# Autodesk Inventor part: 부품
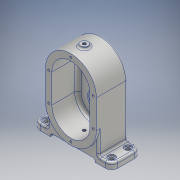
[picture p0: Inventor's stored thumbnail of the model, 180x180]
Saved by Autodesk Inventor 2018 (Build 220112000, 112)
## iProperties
Created: 2021-05
Part Number: 부품
Material: 알루미늄 6061
Document SubType Name: Modeling
Designer: admin
Density: 2.7 g/cm^3
Appearance: 알루미늄 - 평지
Mass: 756.755 g
Surface Area: 581.829 cm^2
Volume: 280.28 cm^3
Author: admin
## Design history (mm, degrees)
sketch "스케치1"
  geometry: L1 (85.4, 0)-(-85.4, 0) reference; L2 (0, -74.9)-(0, 109.9) reference; L3 (40, 43.5)-(40, -38.5); L4 (40, -38.5)-(61, -38.5); L5 (61, -38.5)-(61, -48.5); L6 (61, -48.5)-(35, -48.5); L7 (35, -48.5)-(35, -43.5); L8 (35, -43.5)-(0, -43.5); L9 (-40, 43.5)-(-40, -38.5); L10 (-40, -38.5)-(-61, -38.5); L11 (-61, -38.5)-(-61, -48.5); L12 (-61, -48.5)-(-35, -48.5); L13 (-35, -48.5)-(-35, -43.5); L14 (-35, -43.5)-(0, -43.5); L15 (40, 43.5)-(-40, 43.5); A1 r 40 centre (0, 43.5) between (40, 43.5) and (-40, 43.5); 1 further point
  constraints: 26 end point, 6 symmetric about line, 5 perpendicular, 2 point on circle, 1 centre point, 1 horizontal, 1 midpoint, 1 point on line, 1 vertical, 1 other
  dimensions: "d0" = 70 distance between parallel lines of L13 L7; "d1" = 10 distance between parallel lines of L6 L4; "d2" = 122 distance between parallel lines of L11 L5; "d4" = 5 distance of L12.end L13.end; "d5" = 80 distance of L3.start L9.start; "d6" = 92 distance between parallel lines of L12 L15
extrude "돌출1" new body sketch "스케치1" stored distance "d7" = 46; taper "d8" = 0 deg
sketch "스케치2"
  geometry: L1 (40, -43.5)-(40, 38.5) reference; L2 (40, 38.5)-(61, 38.5) reference; L3 (61, 38.5)-(61, 48.5) reference; L4 (61, 48.5)-(35, 48.5) reference; L5 (35, 48.5)-(35, 43.5) reference; L6 (35, 43.5)-(-35, 43.5) reference; L7 (-35, 43.5)-(-35, 48.5) reference; L8 (-35, 48.5)-(-61, 48.5) reference; L9 (-61, 48.5)-(-61, 38.5) reference; L10 (-61, 38.5)-(-40, 38.5) reference; L11 (-40, 38.5)-(-40, -43.5) reference; L12 (-85.4, 0)-(85.4, 0) reference; L13 (0, 74.9)-(0, -109.9) reference; L14 (0, 1.5)-(0, -43.5); L15 (26, 1.5)-(26, -43.5); L16 (-26, -43.5)-(-26, 1.5); A1 r 40 centre (0, -43.5) between (-40, -43.5) and (40, -43.5) reference; A2 r 26 centre (0, 1.5) between (26, 1.5) and (-26, 1.5); A3 r 26 centre (0, -43.5) between (-26, -43.5) and (26, -43.5); 2 further points
  constraints: 8 end point, 4 point on circle, 4 tangent, 2 centre point, 2 point on line, 1 coincident, 1 midpoint, 1 parallel
  dimensions: "d9" = 26 radius of A3; "d11" = 45 distance of L14.start A1.centre
extrude "돌출2" join sketch "스케치2" distance "d12" = 8; taper "d13" = 0 deg
sketch "스케치3"
  geometry: L1 (26, -43.5)-(26, 1.5) reference; L2 (-26, 1.5)-(-26, -43.5) reference; L3 (-85.4, 0)-(85.4, 0) reference; L4 (0, 74.9)-(0, -109.9) reference; L5 (26, -43.5)-(26, 1.5) reference; L6 (26, -13.5)-(-26, -13.5); L7 (-26, -13.5)-(-26, 1.5); L8 (-26, 1.5)-(26, 1.5); L9 (26, 1.5)-(26, -13.5); A1 r 26 centre (0, 1.5) between (26, 1.5) and (-26, 1.5) reference; A2 r 26 centre (0, -43.5) between (-26, -43.5) and (26, -43.5) reference; A3 r 26 centre (0, 1.5) between (26, 1.5) and (-26, 1.5); 1 further point
  constraints: 8 end point, 2 parallel, 2 point on circle, 1 centre point, 1 coincident, 1 horizontal, 1 perpendicular, 1 point on line
  dimensions: "d14" = 30 distance from line of L6 A2.centre
extrude "돌출3" join sketch "스케치3" distance "d15" = 3; taper "d16" = 0 deg
sketch "스케치4"
  geometry: L1 (-40, 43.5)-(-40, -38.5) reference; L2 (-40, -38.5)-(-61, -38.5) reference; L3 (-61, -38.5)-(-61, -48.5) reference; L4 (-61, -48.5)-(-35, -48.5) reference; L5 (-35, -48.5)-(-35, -43.5) reference; L6 (-35, -43.5)-(35, -43.5) reference; L7 (35, -43.5)-(35, -48.5) reference; L8 (35, -48.5)-(61, -48.5) reference; L9 (61, -48.5)-(61, -38.5) reference; L10 (61, -38.5)-(40, -38.5) reference; L11 (40, -38.5)-(40, 43.5) reference; L12 (-85.4, 0)-(85.4, 0) reference; L13 (0, -74.9)-(0, 109.9) reference; L14 (0, 43.5)-(0, -1.5); L15 (-40, 43.5)-(-40, -1.5); L16 (40, -1.5)-(40, 43.5); A1 r 40 centre (0, 43.5) between (40, 43.5) and (-40, 43.5) reference; A2 r 40 centre (0, 43.5) between (40, 43.5) and (-40, 43.5); A3 r 40 centre (0, -1.5) between (-40, -1.5) and (40, -1.5); 2 further points
  constraints: 8 end point, 4 point on circle, 4 tangent, 2 centre point, 1 concentric, 1 midpoint, 1 parallel, 1 point on line
  dimensions: "d17" = 45 distance of L14.end L14.start
extrude "돌출4" join sketch "스케치4" distance "d18" = 3; taper "d19" = 0 deg
sketch "스케치5"
  geometry: L1 (-40, 43.5)-(-40, -1.5) reference; L2 (40, -1.5)-(40, 43.5) reference; L3 (0, -74.9)-(0, 109.9) reference; L4 (-85.4, 0)-(85.4, 0) reference; L5 (0, -1.5)-(0, 43.5); L6 (30, -1.5)-(30, 43.5); L7 (-30, 43.5)-(-30, -1.5); A1 r 40 centre (0, -1.5) between (-40, -1.5) and (40, -1.5) reference; A2 r 40 centre (0, 43.5) between (40, 43.5) and (-40, 43.5) reference; A3 r 30 centre (0, -1.5) between (-30, -1.5) and (30, -1.5); A4 r 30 centre (0, 43.5) between (30, 43.5) and (-30, 43.5); 2 further points
  constraints: 8 end point, 4 point on circle, 4 tangent, 2 centre point, 1 midpoint, 1 parallel, 1 perpendicular
  dimensions: "d20" = 30 radius of A4
extrude "돌출5" cut sketch "스케치5" distance "d21" = 41; taper "d22" = 0 deg
sketch "스케치6"
  geometry: L1 (30, 43.5)-(30, -1.5) reference; L2 (-30, -1.5)-(-30, 43.5) reference; L3 (-85.4, 0)-(85.4, 0) reference; L4 (0, -74.9)-(0, 109.9) reference; C1 r 14 at (0, 43.5); C2 r 14 at (0, -1.5); A1 r 30 centre (0, 43.5) between (30, 43.5) and (-30, 43.5) reference; A2 r 30 centre (0, -1.5) between (-30, -1.5) and (30, -1.5) reference; 1 further point
  constraints: 2 centre point, 2 coincident
  dimensions: "d23" = 28 diameter of C1; "d24" = 28 diameter of C2
extrude "돌출6" cut sketch "스케치6" distance "d25" = 8; taper "d26" = 0 deg
sketch "스케치7"
  geometry: C1 r 14 at (0, 0) reference; C2 r 11 at (0, 0); 1 further point
  constraints: 1 centre point, 1 coincident
  dimensions: "d27" = 22 diameter of C2
extrude "돌출7" cut sketch "스케치7" distance "d28" = 4; taper "d29" = 0 deg
sketch "스케치8"
  geometry: L1 (26, -13.5)-(-26, -13.5) reference; L2 (-26, -13.5)-(-26, -43.5) reference; L3 (26, -43.5)-(26, -13.5) reference; C1 r 14 at (0, -43.5); A1 r 26 centre (0, -43.5) between (-26, -43.5) and (26, -43.5) reference; 1 further point
  constraints: 1 centre point, 1 coincident
  dimensions: "d30" = 28 diameter of C1
extrude "돌출8" cut sketch "스케치8" distance "d31" = 4; taper "d32" = 0 deg
sketch "스케치9"
  geometry: L1 (23, -15.5)-(23, 12.5) reference; L2 (15, -15.5)-(15, 12.5) reference; L3 (23, -1.5)-(23, -1.5) reference; L4 (23, -1.5)-(34, -1.5) reference; L5 (34, -1.5)-(34, -1.5) reference; L6 (23, -1.5)-(34, -1.5) reference; L7 (23, 43.5)-(-26, 43.5) reference; L8 (23, -38.5)-(23, 43.5) reference; L9 (-23, -38.5)-(23, -38.5) reference; L10 (-23, -1.5)-(-23, -38.5) reference; L11 (-23, -1.5)-(-26, -1.5) reference; L12 (-26, 43.5)-(-26, -1.5) reference; L13 (0, -74.9)-(0, 109.9) reference; L14 (15, 12.5)-(23, 12.5) reference; L15 (15, -15.5)-(23, -15.5) reference; L16 (-26, -1.5)-(15, -1.5) reference; L17 (0, -1.5)-(23, -1.5); L18 (23, -1.5)-(34, -1.5) reference; L19 (23, -1.5)-(27, -1.5); L20 (27, -1.5)-(27, 5.5); L21 (24, 8.5)-(23, 8.5); L22 (23, 8.5)-(23, -1.5); A1 r 3 centre (24, 5.5) between (27, 5.5) and (24, 8.5); 2 further points
  constraints: 10 end point, 4 point on line, 2 parallel, 2 point on circle, 2 tangent, 1 centre point, 1 collinear, 1 horizontal, 1 perpendicular
  dimensions: "d34" = 4 distance of point (27, 8.5) L21.end; "d35" = 20 diameter of L21 L17; "d36" = 3 radius of A1
revolve "회전1" sketch "스케치9" stored, may be unused: angle "d37" = 90 deg
node "작업 평면1"
sketch "스케치10"
  geometry: L1 (-120.4, -23)-(50.4, -23) reference; L2 (-35, -61)-(-35, 23) reference; L3 (-75, -49)-(5, -49) reference; C1 r 6 at (-35, -28); 1 further point
  constraints: 1 centre point, 1 point on line
  dimensions: "d39" = 21 distance from line of L3 C1.centre; "d40" = 12 diameter of C1
extrude "돌출9" join sketch "스케치10" stored distance "d41" = 4; taper "d42" = 0 deg
fillet "모깎기1" dims "d43" = 10
sketch "스케치11"
  geometry: L1 (-101, 10)-(-101, 36) reference; L2 (-80, 0)-(-91, 0) reference; L3 (-80, 0)-(-80, 46) reference; L4 (-91, 46)-(-80, 46) reference; L5 (0, 46)-(11, 46) reference; L6 (0, 0)-(0, 46) reference; L7 (11, 0)-(0, 0) reference; L8 (21, 10)-(21, 36) reference; A1 r 10 centre (-91, 36) between (-91, 46) and (-101, 36) reference; A2 r 10 centre (-91, 10) between (-101, 10) and (-91, 0) reference; A3 r 10 centre (11, 36) between (21, 36) and (11, 46) reference; A4 r 10 centre (11, 10) between (11, 0) and (21, 10) reference; 5 further points
  constraints: 4 coincident
hole "구멍1" sketch "스케치11" at (-91, 36), (-91, 10), (11, 10), (11, 36) diameter "d44" = 6.6; stored, may be unused: countersink angle "d48" = 90 deg, drill point angle "d50" = 0 deg; dims "d45" = 6, "d46" = 11, "d47" = 2, "d49" = 8
sketch "스케치12"
  geometry: L1 (30, 43.5)-(30, -1.5) reference; L2 (-30, -1.5)-(-30, 43.5) reference; L3 (-40, 43.5)-(-40, -1.5) reference; L4 (40, -1.5)-(40, 43.5) reference; L5 (0, -75.5)-(0, 113.5) reference; L6 (-85.4, 0)-(85.4, 0) reference; L7 (0, -1.5)-(0, 43.5); L8 (35, -1.5)-(35, 43.5); L9 (-35, 43.5)-(-35, -1.5); A1 r 30 centre (0, 43.5) between (30, 43.5) and (-30, 43.5) reference; A2 r 30 centre (0, -1.5) between (-30, -1.5) and (30, -1.5) reference; A3 r 40 centre (0, -1.5) between (-40, -1.5) and (40, -1.5) reference; A4 r 40 centre (0, 43.5) between (40, 43.5) and (-40, 43.5) reference; A5 r 35 centre (0, -1.5) between (-35, -1.5) and (35, -1.5); A6 r 35 centre (0, 43.5) between (35, 43.5) and (-35, 43.5); 8 further points
  constraints: 8 end point, 6 point on circle, 4 coincident, 4 tangent, 2 centre point, 1 collinear, 1 midpoint, 1 parallel
  dimensions: "d51" = 35 radius of A6
hole "구멍2" sketch "스케치12" at (0, 78.5), (0, -36.5), (35, -1.5), (-35, -1.5), (35, 43.5), (-35, 43.5) diameter "d52" = 3.242; stored, may be unused: countersink angle "d56" = 90 deg, drill point angle "d58" = 118 deg; dims "d53" = 8, "d54" = 11, "d55" = 2, "d57" = 10
sketch "스케치13" dims "d59" = 40
  geometry: L1 (26, -13.5)-(-26, -13.5) reference; L2 (-26, -13.5)-(-26, -43.5) reference; L3 (26, -43.5)-(26, -13.5) reference; L4 (-85.4, 0)-(85.4, 0) reference; L5 (0, 75.5)-(0, -113.5) reference; C1 r 14 at (0, -43.5) reference; A1 r 26 centre (0, -43.5) between (-26, -43.5) and (26, -43.5) reference; 7 further points
  constraints: 3 coincident, 1 point on line, 1 vertical alignment, 16 other
  dimensions: "d62" = 360 deg dimension on point (0, -43.5) point (0, -63.5) (derived)
hole "구멍3" sketch "스케치13" at (0, -63.5), (17.321, -33.5), (-17.321, -33.5) diameter "d64" = 3.242; stored, may be unused: countersink angle "d68" = 90 deg, drill point angle "d70" = 118 deg; dims "d65" = 8, "d66" = 11, "d67" = 2, "d69" = 10
sketch "스케치14"
  geometry: C1 r 6 at (0, 0) reference; 2 further points
  constraints: 1 coincident
hole "구멍4" sketch "스케치14" at (0, 0) diameter "d71" = 4.917; stored, may be unused: countersink angle "d75" = 90 deg, drill point angle "d77" = 0 deg; dims "d72" = 30, "d73" = 11, "d74" = 2, "d76" = 30
sketch "스케치15"
  geometry: L1 (70, -46)-(70, 0) reference; L2 (0, 0)-(70, 0) reference; L3 (0, -46)-(0, 0) reference; L4 (70, -46)-(0, -46) reference; L5 (35, -61)-(35, 23) reference; L6 (120.4, -23)-(-50.4, -23) reference; L7 (-5, -49)-(75, -49) reference; C1 r 6 at (35, -28); 1 further point
  constraints: 1 centre point, 1 point on line
  dimensions: "d78" = 21 distance from line of C1.centre L7; "d79" = 12 diameter of C1
extrude "돌출10" cut sketch "스케치15" distance "d80" = 1; taper "d81" = 0 deg
sketch "스케치16"
  geometry: C1 r 6 at (0, 0) reference; 2 further points
  constraints: 1 coincident
hole "구멍5" sketch "스케치16" at (0, 0) diameter "d82" = 4.917; stored, may be unused: countersink angle "d86" = 90 deg, drill point angle "d88" = 0 deg; dims "d83" = 30, "d84" = 11, "d85" = 2, "d87" = 30
chamfer "모따기1" distance "d89" = 1; stored, may be unused: second distance "d90" = 2, angle "d91" = 45 deg
sketch "스케치17"
  geometry: L1 (-26, -43.5)-(-26, 1.5) reference; L2 (26, 1.5)-(26, -43.5) reference; L3 (-51, 38.5)-(-51, 48.5) reference; L4 (-51, 38.5)-(-40, 38.5) reference; L5 (-40, 38.5)-(-40, -43.5) reference; L6 (40, -43.5)-(40, 38.5) reference; L7 (40, 38.5)-(51, 38.5) reference; L8 (51, 48.5)-(51, 38.5) reference; L9 (51, 48.5)-(35, 48.5) reference; L10 (35, 48.5)-(35, 43.5) reference; L11 (35, 43.5)-(-35, 43.5) reference; L12 (-35, 43.5)-(-35, 48.5) reference; L13 (-35, 48.5)-(-51, 48.5) reference; L14 (0, 75.5)-(0, -113.5) reference; L15 (-85.4, 0)-(85.4, 0) reference; A1 r 26 centre (0, -43.5) between (-26, -43.5) and (26, -43.5) reference; A2 r 26 centre (0, 1.5) between (26, 1.5) and (-26, 1.5) reference; A3 r 40 centre (0, -43.5) between (-40, -43.5) and (40, -43.5) reference; 2 further points
  constraints: 1 point on line, 1 other
  dimensions: "d92" = 12 distance from line of L9 point (0, 36.5)
feature "엠보싱1" sketch "스케치17" dims "d0" = 70, "d1" = 10, "d2" = 122, "d4" = 5, "d5" = 80, "d6" = 92, "d93" = 0.5, "d94" = 0
fillet "모깎기2" dims "d95" = 0.3
fillet "모깎기3" dims "d96" = 5
fillet "모깎기4" dims "d97" = 3
fillet "모깎기5" dims "d98" = 3
node "솔리드1"
node "투영된 루프1"
node "투영된 루프2"
node "투영된 루프3"
node "투영된 루프4"
node "투영된 루프5"
node "투영된 루프6"
node "투영된 루프7"
node "투영된 루프8"
node "투영된 루프9"
node "투영된 루프10"
node "투영된 루프11"
node "투영된 루프12"
node "투영된 루프13"
node "투영된 루프14"
node "투영된 루프15"
node "투영된 루프16"
node "투영된 루프17"
node "투영된 루프18"
